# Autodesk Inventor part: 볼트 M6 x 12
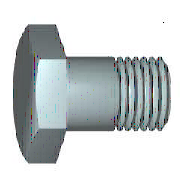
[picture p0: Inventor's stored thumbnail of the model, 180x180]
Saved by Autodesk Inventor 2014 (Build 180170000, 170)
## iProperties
Created: 2012-02
Part Number: 볼트 M6 x 12
Material: 스테인리스강
Description: 6각 머리 나사. 제품 등급 C
Document SubType Name: Modeling
Standard: ISO 4018
Designer: mduedu
Standard Revision: Third edition 1999-08-15
Standards Organization: ISO
Language: ko-KR
Size Designation: M6 x 12
Categories: <MemberInstance><Categories><Category DisplayName="조임쇠" InternalName="e4da775c-781d-43d5-af7c-5136215cf5a6" Mnemonic="FSTN"><Category DisplayName="볼트" InternalN
Density: 8.08 g/cm^3
Appearance: 반광택
IsCustomPart: 0
Author: mduedu
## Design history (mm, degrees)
node "WorkPlane1"
node "WorkPoint1"
node "MSC_A1"
node "MSC_PF1"
node "MSC_PT1"
body "Solid1"
node "스케치1"
sketch "스케치2"
  geometry: L1 (-5, 2.887)-(-5, -2.887); L2 (0, 5.773)-(-5, 2.887); L3 (5, 2.887)-(0, 5.773); L4 (5, -2.887)-(5, 2.887); L5 (0, -5.773)-(5, -2.887); L6 (-5, -2.887)-(0, -5.773); C1 r 5 at (0, 0); 1 further point
  constraints: 12 end point, 6 tangent, 2 parallel, 2 vertical, 1 centre point
  dimensions: "d1" = 10 diameter of C1 (= ParS); "d29" = 0 distance of point (0, 0) C1.centre; "d30" = 0 distance of C1.centre point (0, 0)
extrude "돌출1" new body sketch "스케치2" distance "d6" = 4 (= ParK); taper "d7" = 0 deg
revolve "회전1" stored, may be unused: angle "d14" = 360 deg
revolve "회전2" stored, may be unused: angle "d21" = 360 deg
chamfer "모따기1" distance "d22" = 0.5 (= 0.5 x PTC); stored, may be unused: second distance "d23" = 0.5 (= 0.5 x PTC), angle "d39" = 45 deg
fillet "모깎기1" dims "d24" = 0.25 (= r)
feature "스레드1" dims "d32" = 0, "b" = 10 (= NLG - 2 x PTC)
sketch "스케치3"
  geometry: L1 (5, 4)-(5.873, 4); L2 (5.873, 3.496)-(5, 4); L3 (5.873, 4)-(5.873, 3.496); L4 (0, -0.8)-(0, 4.8) reference; L5 (5.773, 0)-(5.773, 4) reference
  constraints: 6 end point, 1 horizontal, 1 vertical
  dimensions: "d25" = 0.1 distance between parallel lines of L5 L3; "d26" = 0 distance from line of L5.end L1; "d27" = 60 deg angle of L3 L2; "d28" = 5 distance from line of L4 L1.start (= 0.5 x ParS)
sketch "스케치4"
  geometry: L1 (0, -12)-(0, 0); L2 (-3, -12)-(0, -12); L3 (-3, 0)-(-3, -12); L4 (0, 0)-(-3, 0); L5 (0, -12)-(0, 0); L6 (-3.6, 0)-(0.6, 0) reference; L7 (0, -14.4)-(0, 2.4) reference
  constraints: 10 end point, 2 horizontal, 2 vertical
  dimensions: "d18" = 3 distance of L1.start L2.start (= 0.5 x NND); "d20" = 12 distance of L3.start L2.start (= NLG); "d33" = 0 distance between parallel lines of L7 L1; "d34" = 0 distance between parallel lines of L6 L4
other parameters: "NND" = 6 [user parameter; used in 2 equation terms], "NLG" = 12 [user parameter; used in 2 equation terms], "PTC" = 1 [user parameter; used in 3 equation terms], "ParK" = 4 [user parameter; used in 1 equation term], "ParS" = 10 [user parameter; used in 3 equation terms], "msp_es" = 5.77367 (= 0.577367 x ParS) [user parameter], "r" = 0.25 [user parameter; used in 1 equation term], "d2" = 15 (derived), "d4" = 17.32102 (derived), "d8" = 15 (derived), "d10" = 0 (derived), "d12" = 30 deg (derived), "d15" = 0 (derived), "d37" = 0, "d38" = 0, "d40" = 0, "d41" = 0, "d42" = 0, "THREADDIA" = 6 (= NND) [user parameter]
